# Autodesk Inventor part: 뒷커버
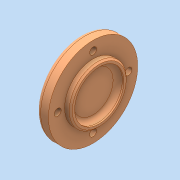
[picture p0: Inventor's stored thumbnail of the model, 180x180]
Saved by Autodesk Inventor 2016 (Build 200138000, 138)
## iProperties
Created: 2024-08
Part Number: 뒷커버
Material: 일반
Document SubType Name: Modeling
Designer: pc-7
Density: 1 g/cm^3
Appearance: 기본값
Author: jhkim
Sending System: Autodesk Inventor 2025
Preprocessor: ST-DEVELOPER v20
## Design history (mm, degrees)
node "뒷커버1"
node "솔리드2"
node "솔리드1"
